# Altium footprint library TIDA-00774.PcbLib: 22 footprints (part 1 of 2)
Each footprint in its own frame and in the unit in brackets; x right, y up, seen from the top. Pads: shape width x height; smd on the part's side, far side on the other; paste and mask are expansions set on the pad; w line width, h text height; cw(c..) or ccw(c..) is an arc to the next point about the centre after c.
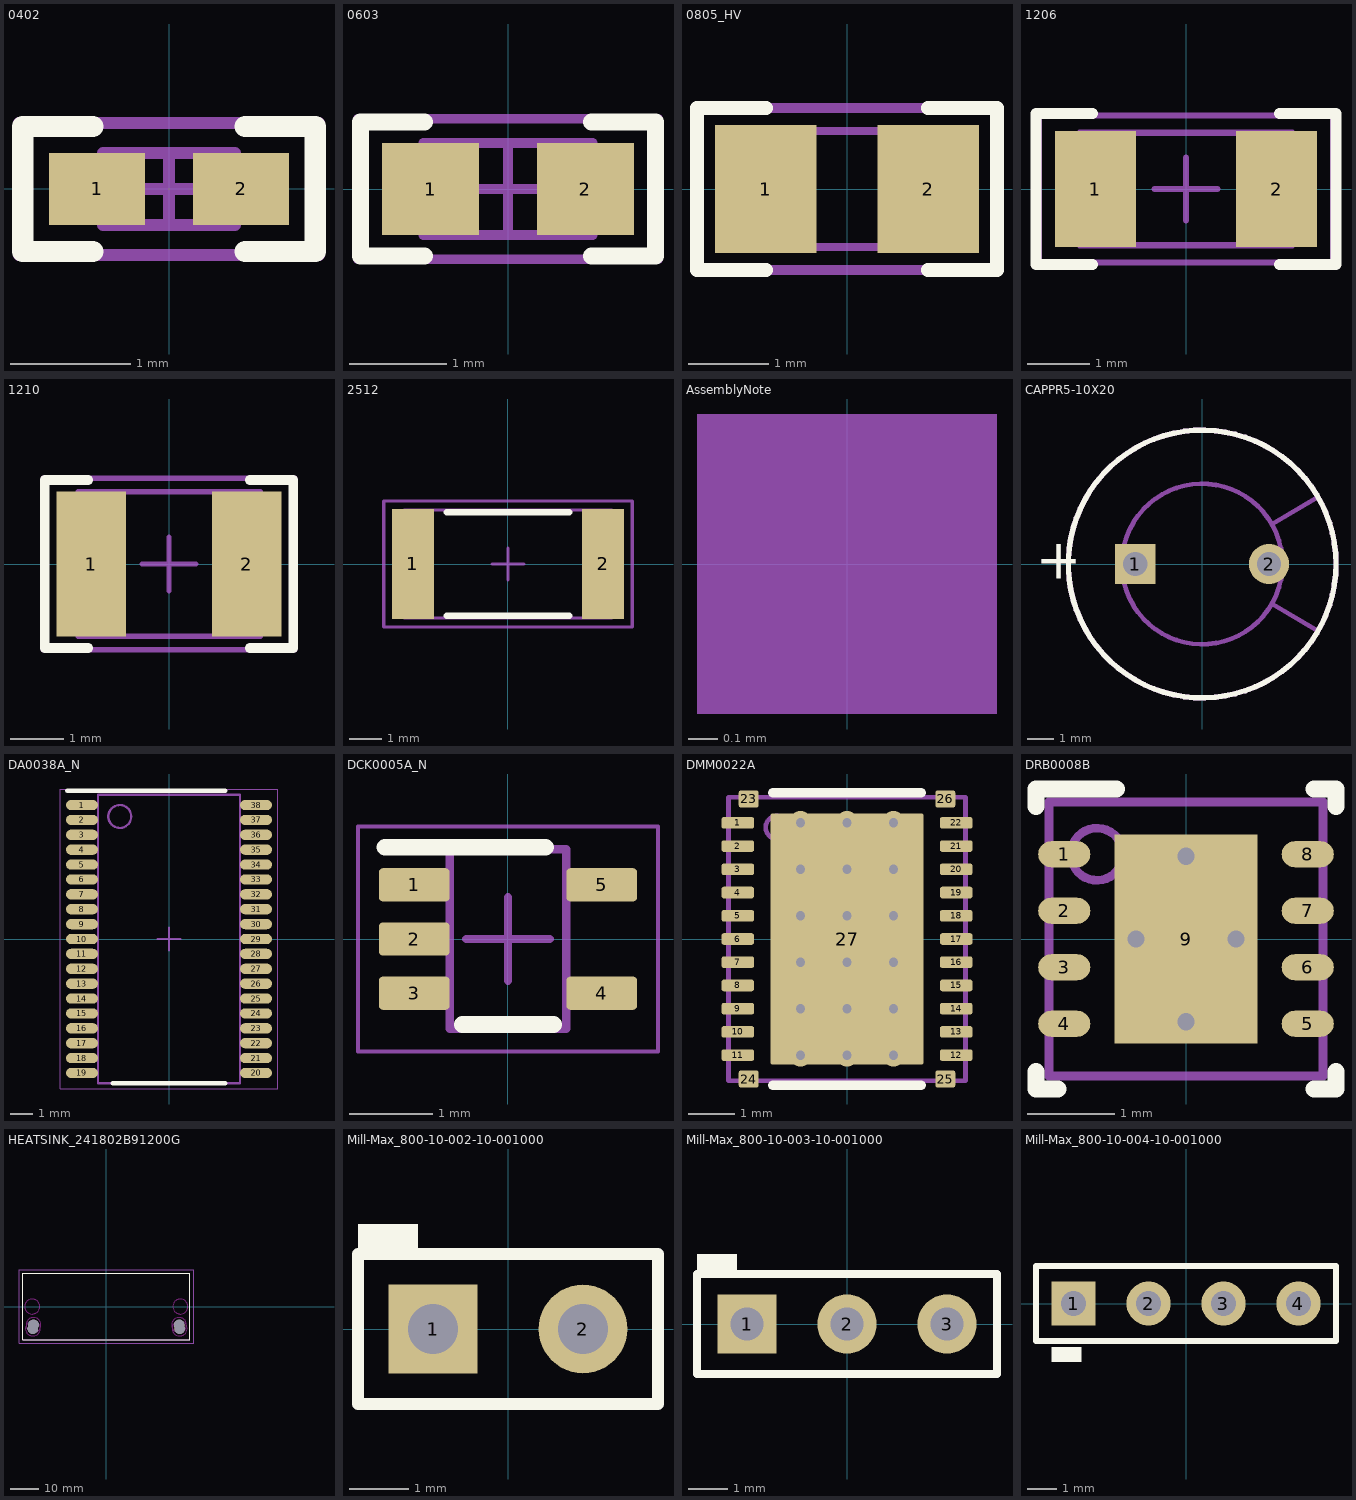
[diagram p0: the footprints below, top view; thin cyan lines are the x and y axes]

## 0402 [mm] "0402 from SM-752 data"
height 0.6
pads (2):
  rect 0.8x0.6 smd: 1(-0.6,0) 2(0.6,0)
Top Overlay:
  lines w0.178: -0.635,-0.521 -1.219,-0.521 -1.219,0.521 -0.635,0.521 ; 0.635,-0.521 1.219,-0.521 1.219,0.521 0.635,0.521
Mechanical 5:
  lines w0.1: -1.25,-0.55 1.25,-0.55 1.25,0.55 -1.25,0.55 -1.25,-0.55
  text ".Designator" at -1.117,-0.305 h0.61
Mechanical 13:
  lines w0.1: -0.35,-0.3 -0.35,0.3 ; 0.35,-0.3 0.35,0.3 ; -0.55,-0.3 -0.55,0.3 0.55,0.3 0.55,-0.3 -0.55,-0.3
Mechanical 15:
  lines w0.1: -0.3,0 0.3,0 ; 0,-0.3 0,0.3 ; -1.25,-0.55 -1.25,0.55 1.25,0.55 1.25,-0.55 -1.25,-0.55
3D body: height 0.6, standoff 0, extent -0.549,-0.299 -0.351,0.299
3D body: height 0.6, standoff 0, extent -0.349,-0.299 0.349,0.299
3D body: height 0.6, standoff 0, extent 0.351,-0.299 0.549,0.299

## 0603 [mm] "0603 from SM-752 data"
height 1
pads (2):
  rect 1x0.95 smd: 1(-0.8,0) 2(0.8,0)
Top Overlay:
  lines w0.178: -0.864,-0.691 -1.524,-0.691 -1.524,0.693 -0.864,0.693 ; 0.864,-0.691 1.524,-0.691 1.524,0.693 0.864,0.693
Mechanical 5:
  lines w0.1: -1.55,-0.725 1.55,-0.725 1.55,0.725 -1.55,0.725 -1.55,-0.725
  text ".Designator" at -1.397,-0.381 h0.76
Mechanical 13:
  lines w0.1: -0.55,-0.475 -0.55,0.475 ; 0.55,-0.475 0.55,0.475 ; -0.875,-0.475 -0.875,0.475 0.875,0.475 0.875,-0.475 -0.875,-0.475
Mechanical 15:
  lines w0.1: -0.475,0 0.475,0 ; 0,-0.475 0,0.475 ; -1.55,-0.725 -1.55,0.725 1.55,0.725 1.55,-0.725 -1.55,-0.725
3D body: height 1, standoff 0, extent 0.551,-0.474 0.874,0.474
3D body: height 1, standoff 0, extent -0.549,-0.474 0.549,0.474
3D body: height 1, standoff 0, extent -0.874,-0.474 -0.551,0.474

## 0805_HV [mil] "0805 with 30mil clearance between pads"
height 57.09
pads (2):
  rect 50x63 smd: 1(-40,0) 2(40,0)
Top Overlay:
  lines w7: -40,-40 -74,-40 -74,0 -74,40 -40,40 ; 40,-40 74,-40 74,0 74,40 40,40
Mechanical 5:
  lines w5: -74,-40 74,-40 74,40 -74,40 -74,-40
  text ".Designator" at -64,-17 h35
Mechanical 13:
  lines w3.94: -25.59,-28.54 -25.59,28.54 ; 25.59,-28.54 25.59,28.54 ; -43.31,-28.54 43.31,-28.54 43.31,28.54 -43.31,28.54 -43.31,-28.54
3D body: height 57.09, standoff 0, extent -43.29,-28.52 -25.61,28.52
3D body: height 57.09, standoff 0, extent -25.57,-28.52 25.57,28.52
3D body: height 57.09, standoff 0, extent 25.61,-28.52 43.29,28.52

## 1206 [mm] "1206 from SM-752 data"
height 1.35
pads (2):
  rect 1.3x1.85 smd: 1(-1.45,0) 2(1.45,0)
Top Overlay:
  lines w0.178: -1.5,-1.21 -2.4,-1.21 -2.4,1.21 -1.5,1.21 ; 1.5,-1.21 2.4,-1.21 2.4,1.21 1.5,1.21
Mechanical 5:
  lines w0.1: -1.7,-0.9 -1.7,0.9 1.7,0.9 1.7,-0.9 -1.7,-0.9
  text ".Designator" at -1.475,-0.4 h0.76
Mechanical 13:
  lines w0.1: -1.2,-0.9 -1.2,0.9 ; 1.2,-0.9 1.2,0.9 ; -1.7,-0.9 -1.7,0.9 1.7,0.9 1.7,-0.9 -1.7,-0.9
Mechanical 15:
  lines w0.1: -0.5,0 0.5,0 ; 0,-0.5 0,0.5 ; -2.35,-1.175 -2.35,1.175 2.35,1.175 2.35,-1.175 -2.35,-1.175
3D body: height 1.35, standoff 0, extent 1.201,-0.899 1.699,0.899
3D body: height 1.35, standoff 0, extent -1.199,-0.899 1.199,0.899
3D body: height 1.35, standoff 0, extent -1.699,-0.899 -1.201,0.899

## 1210 [mm] "1210 from SM-752 data"
height 1.35
pads (2):
  rect 1.3x2.7 smd: 1(-1.45,0) 2(1.45,0)
Top Overlay:
  lines w0.178: -1.511,-1.568 -2.316,-1.568 -2.316,1.568 -1.511,1.568 ; 1.511,-1.568 2.316,-1.568 2.316,1.568 1.511,1.568
Mechanical 5:
  lines w0.1: -1.7,-1.35 1.7,-1.35 1.7,1.35 -1.7,1.35 -1.7,-1.35
  text ".Designator" at -1.4,-0.375 h0.76
Mechanical 13:
  lines w0.1: -1.2,-1.35 -1.2,1.35 ; 1.2,-1.35 1.2,1.35 ; -1.7,-1.35 -1.7,1.35 1.7,1.35 1.7,-1.35 -1.7,-1.35
Mechanical 15:
  lines w0.1: -0.5,0 0.5,0 ; 0,-0.5 0,0.5 ; -2.35,-1.6 -2.35,1.6 2.35,1.6 2.35,-1.6 -2.35,-1.6
3D body: height 1.35, standoff 0, extent -1.699,-1.349 -1.201,1.349
3D body: height 1.35, standoff 0, extent -1.199,-1.349 1.199,1.349
3D body: height 1.35, standoff 0, extent 1.201,-1.349 1.699,1.349

## 2512 [mm] "Chip Resistor, Body 6.3x3.2mm, IPC Medium Density"
height 0.71
pads (2):
  rect 1.3x3.4 smd: 1(-2.95,0) 2(2.95,0)
Top Overlay:
  lines w0.2: -1.9,-1.6 1.9,-1.6 ; -1.9,1.6 1.9,1.6
Mechanical 5:
  lines w0.1: -3.225,-1.675 -3.225,1.675 3.225,1.675 3.225,-1.675 -3.225,-1.675
  text ".Designator" at -0.686,-0.305 h0.64
Mechanical 13:
  lines w0.1: -2.463,-1.675 -2.463,1.675 ; 2.463,-1.675 2.463,1.675 ; -3.225,-1.675 -3.225,1.675 3.225,1.675 3.225,-1.675 -3.225,-1.675
Mechanical 15:
  lines w0.1: -0.5,0 0.5,0 ; 0,-0.5 0,0.5 ; -3.85,-1.95 -3.85,1.95 3.85,1.95 3.85,-1.95 -3.85,-1.95
3D body: height 0.71, standoff 0, extent 2.464,-1.674 3.224,1.674
3D body: height 0.71, standoff 0, extent -2.462,-1.674 2.462,1.674
3D body: height 0.71, standoff 0, extent -3.224,-1.674 -2.464,1.674

## AssemblyNote [mm] "Assembly Note"
Mechanical 5:
  rectangle: -0.508,-0.508 0.508,0.508
  text ".Designator" at -4.191,-0.508 h0.64
  text ".Comment" at 1.143,-0.508 h0.64

## CAPPR5-10X20 [mm] "Capacitor, Electrolytic, Radial; Body 10 x 20 mm (Dia.xH typ); Pin Spacing 5 mm (typ)"
height 22
pads (2):
  rect 1.5x1.5 hole 0.9: 1(-2.5,0)
  round 1.5 hole 0.9: 2(2.5,0)
Top Overlay:
  circle w0.2: c0,0 r5
  text "+" at -6.208,-0.559 h1.5
Mechanical 5:
  circle w0.2: c0,0 r5
  text ".Designator" at 0.446,0.254 h0.64
  text "+" at -5.65,-0.025 h0.64
Mechanical 13:
  circle w0.178: c0,0 r3
  circle w0.178: c-2.5,0 r0.3
  circle w0.178: c2.5,0 r0.3
  lines w0.178: 2.623,-1.5 4.33,-2.5 cw(c0,0) 4.33,2.5 ; 2.623,1.5 4.33,2.5
3D body: height 22, standoff 0, extent 2.597,-2.5 5.001,2.5
3D body: height 22, standoff 0, extent -5,-5 4.329,5
3D body: height 22, standoff 0, extent -2.999,-2.999 2.999,2.999
3D body: height 1, standoff -2.54, extent -2.799,-0.299 -2.201,0.299
3D body: height 1, standoff -2.54, extent 2.201,-0.299 2.799,0.299

## DA0038A_N [mm] "TSOP, 38-Leads, Body 12.6x6.2mm (max), Pitch 0.65mm, IPC Medium Density"
height 1.2
pads (38):
  oval 1.4x0.45 smd: 1(-3.8,5.85) 2(-3.8,5.2) 3(-3.8,4.55) 4(-3.8,3.9) 5(-3.8,3.25) 6(-3.8,2.6) 7(-3.8,1.95) 8(-3.8,1.3) 9(-3.8,0.65) 10(-3.8,0) 11(-3.8,-0.65) 12(-3.8,-1.3) 13(-3.8,-1.95) 14(-3.8,-2.6) 15(-3.8,-3.25) 16(-3.8,-3.9) 17(-3.8,-4.55) 18(-3.8,-5.2) 19(-3.8,-5.85) 20(3.8,-5.85) 21(3.8,-5.2) 22(3.8,-4.55) 23(3.8,-3.9) 24(3.8,-3.25) 25(3.8,-2.6) 26(3.8,-1.95) 27(3.8,-1.3) 28(3.8,-0.65) 29(3.8,0) 30(3.8,0.65) 31(3.8,1.3) 32(3.8,1.95) 33(3.8,2.6) 34(3.8,3.25) 35(3.8,3.9) 36(3.8,4.55) 37(3.8,5.2) 38(3.8,5.85)
Top Overlay:
  lines w0.2: -4.45,6.475 2.45,6.475 ; -2.45,-6.3 2.45,-6.3
Mechanical 5:
  circle w0.1: c-2.15,5.35 r0.5
  lines w0.1: -3.1,-6.3 3.1,-6.3 3.1,6.3 -3.1,6.3 -3.1,-6.3
  text ".Designator" at -1.8,-0.7 h1
Mechanical 15:
  lines w0.05: -4.75,-6.55 -4.75,6.55 4.75,6.55 4.75,-6.55 -4.75,-6.55
  lines w0.1: -0.5,0 0.5,0 ; 0,-0.5 0,0.5
3D body "DA0038A_L.stp": height 1.2, standoff 0, extent -4.055,-6.25 4.056,6.25

## DCK0005A_N [mm] "SOT353, 5-Leads, Body 2x1.3mm, Pitch 0.65mm, Lead Span 2.1mm, IPC Medium Density"
height 1.1
pads (5):
  rrect25% 0.85x0.4 smd: 1(-1.125,0.65) 2(-1.125,0) 3(-1.125,-0.65) 4(1.125,-0.65) 5(1.125,0.65)
Top Overlay:
  lines w0.2: -1.475,1.1 0.45,1.1 ; -0.55,-1.025 0.55,-1.025
Mechanical 5:
  lines w0.1: -0.7,-1.075 -0.7,1.075 0.7,1.075 0.7,-1.075 -0.7,-1.075
  lines w0.127: -0.865,0.762 -0.853,0.762 ; -0.711,-0.763 -0.853,-0.763 -0.865,-0.763 -0.959,-0.763 -1.143,-0.763 -1.143,-0.538 -0.959,-0.538 -0.865,-0.538 -0.853,-0.538 -0.711,-0.538 ; -0.711,-0.113 -0.853,-0.113 -0.865,-0.113 -0.959,-0.113 -1.143,-0.113 -1.143,0.112 -0.959,0.112 -0.865,0.112 -0.853,0.112 -0.711,0.112 ; -0.711,0.537 -0.853,0.537 -0.865,0.537 -0.959,0.537 -1.143,0.537 -1.143,0.762 -0.959,0.762 -0.711,0.762 ; 0.711,-0.763 0.847,-0.763 0.859,-0.763 0.953,-0.763 1.137,-0.763 1.137,-0.538 0.953,-0.538 0.859,-0.538 0.847,-0.538 0.711,-0.538 ; 0.711,0.537 0.847,0.537 0.859,0.537 0.953,0.537 1.137,0.537 1.137,0.762 0.953,0.762 0.859,0.762 0.847,0.762 0.711,0.762
  text ".Designator" at -0.254,0.914 h0.51
Mechanical 15:
  lines w0.05: -1.8,-1.35 -1.8,1.35 1.8,1.35 1.8,-1.35 -1.8,-1.35
  lines w0.1: -0.5,0 0.5,0 ; 0,-0.5 0,0.5
3D body "DCK0005A.stp": height 0.95, standoff 0, extent -1.14,-1 1.14,1

## DMM0022A [mm] "SON, 27-Leads, Body 5x6mm, Pitch 0.5mm"
height 1.05
pads (35):
  rrect40% 0.7x0.25 smd mask+0.051: 1(-2.35,2.5) 2(-2.35,2) 21(2.35,2) 22(2.35,2.5)
  rrect40% 0.7x0.25 smd mask+0: 3(-2.35,1.5) 4(-2.35,1) 5(-2.35,0.5) 6(-2.35,0) 7(-2.35,-0.5) 8(-2.35,-1) 9(-2.35,-1.5) 10(-2.35,-2) 11(-2.35,-2.5) 12(2.35,-2.5) 13(2.35,-2) 14(2.35,-1.5) 15(2.35,-1) 16(2.35,-0.5) 17(2.35,0) 18(2.35,0.5) 19(2.35,1) 20(2.35,1.5)
  rrect27% 0.43x0.375 smd mask+0.051: 23(-2.115,3.013) 24(-2.115,-3.013) 25(2.115,-3.013) 26(2.115,3.013)
  rrect3% 3.3x5.4 smd paste-1.65: 27(0,0)
  rrect50% 1.41x1.12 on Top Paste: ""(-0.805,-1.98) ""(-0.805,-0.66) ""(-0.805,0.66) ""(-0.805,1.98) ""(0.805,-1.98) ""(0.805,-0.66) ""(0.805,0.66) ""(0.805,1.98)
via 1,0.501 diameter 0.5 hole 0.2
via 1,1.501 diameter 0.5 hole 0.2
via 1,-1.499 diameter 0.5 hole 0.2
via 1,-0.499 diameter 0.5 hole 0.2
via 1,-2.499 diameter 0.5 hole 0.2
via 0,0.501 diameter 0.5 hole 0.2
via 0,1.501 diameter 0.5 hole 0.2
via 0,-1.499 diameter 0.5 hole 0.2
via 0,-0.499 diameter 0.5 hole 0.2
via 0,-2.499 diameter 0.5 hole 0.2
via -1,-2.499 diameter 0.5 hole 0.2
via -1,-0.499 diameter 0.5 hole 0.2
via -1,-1.499 diameter 0.5 hole 0.2
via -1,1.501 diameter 0.5 hole 0.2
via -1,0.501 diameter 0.5 hole 0.2
via -1,2.501 diameter 0.5 hole 0.2
via 1,2.501 diameter 0.5 hole 0.2
via 0,2.501 diameter 0.5 hole 0.2
Top Overlay:
  lines w0.2: -1.6,-3.15 1.6,-3.15 ; -1.6,3.15 1.6,3.15
Mechanical 5:
  circle w0.1: c-1.5,2.4 r0.25
  lines w0.1: -2.55,-3.05 -2.55,3.05 2.55,3.05 2.55,-3.05 -2.55,-3.05
  text ".Designator" at -2,-0.7 h1.85
3D body: height 1.05, standoff 0, extent -2.55,-3.05 2.55,3.05
3D body: height 1.05, standoff 1.05, extent -1.749,2.151 -1.251,2.649

## DRB0008B [mm] "SON, 8-Leads, Body 3x3mm, Pitch 0.65mm, Thermal Pad 2.4x1.65mm, TI Recommended"
height 1
pads (9):
  oval 0.6x0.3 smd: 1(-1.4,0.975) 2(-1.4,0.325) 3(-1.4,-0.325) 4(-1.4,-0.975) 5(1.4,-0.975) 6(1.4,-0.325) 7(1.4,0.325) 8(1.4,0.975)
  rect 1.65x2.4 smd paste-1.2: 9(0,0)
via 0,-0.95 diameter 0.5 hole 0.2
via 0,0.95 diameter 0.5 hole 0.2
via 0.575,0 diameter 0.5 hole 0.2
via -0.575,0 diameter 0.5 hole 0.2
Top Overlay:
  lines w0.2: -1.725,-1.525 -1.725,-1.725 -1.475,-1.725 ; -1.725,1.525 -1.725,1.725 -0.8,1.725 ; 1.475,-1.725 1.725,-1.725 1.725,-1.525 ; 1.475,1.725 1.725,1.725 1.725,1.525
Top Paste:
  rectangle: -0.751,-1.143 0.752,-0.1
  rectangle: -0.751,0.1 0.752,1.143
Mechanical 5:
  circle w0.1: c-1.025,0.975 r0.3
  lines w0.1: -1.575,-1.575 -1.575,1.575 1.575,1.575 1.575,-1.575 -1.575,-1.575
  text ".Designator" at -1.397,-0.889 h0.76
3D body: height 1, standoff 0, extent -1.575,-1.575 1.575,1.575
3D body: height 1.01, standoff 0.5, extent -1.324,0.676 -0.726,1.274

## HEATSINK_241802B91200G [mm] "HEAT SINK, Mechanical part"
height 6.1
pads (4):
  round 3.654 hole 3.654 unplated mask+0.508: ""(-25.4,-7.6) ""(-25.2,-6.4) ""(25.2,-6.4) ""(25.4,-7.6)
Top Layer:
  lines w0.254: 25.168,-7.393 ccw(c25.4,-7.366) 25.524,-7.564
Top Overlay:
  lines w0.178: -28.95,-11.45 28.95,-11.45 28.95,11.45 -28.95,11.45 -28.95,-11.45
Keep-Out Layer:
  circle w0.025: c-25.65,0 r2.589
  circle w0.025: c25.65,0 r2.589
  circle w0.025: c-25.2,-6.4 r2.589
  circle w0.025: c-25.4,-7.6 r2.589
  circle w0.025: c25.2,-6.4 r2.589
  circle w0.025: c25.4,-7.6 r2.589
Mechanical 5:
  lines w0.127: -28.95,-11.45 28.95,-11.45 28.95,11.45 -28.95,11.45 -28.95,-11.45
  text ".Designator" at -0.381,0.909 h1.02
Mechanical 15:
  lines w0.05: -30.22,-12.72 30.22,-12.72 30.22,12.72 -30.22,12.72 -30.22,-12.72
Drill Drawing:
  lines w0.254: 26.5,-9.375 27.325,-10.2 ; 27.25,-6.65 29.65,-6.65 44.538,-6.65 ; 44.613,-10.2 29.725,-10.2 27.325,-10.2 ; 54.85,-16.425 54.342,-15.409 cw(c55.988,-14.399) 57.786,-13.694 ; 54.85,-14.625 55.875,-14.625 ; 54.883,-16.47 ccw(c56.593,-15.59) 58.386,-14.893 ; 55.35,-14.1 55.359,-15.04 ; 55.525,-16.1 56.55,-16.1 ; 56.025,-15.625 56.034,-16.565 ; 56.625,-14.55 67.675,-14.55 ; 56.75,-14.925 56.4,-14.575 56.75,-14.225 ; 57.275,-16.105 67.225,-16.105 ; 57.4,-16.5 57.05,-16.15 57.4,-15.8 ; 57.793,-13.692 58.358,-14.841 ; 66.625,-11.35 67.85,-11.35 ; 66.7,-15.1 67.35,-13.8 ; 66.703,-15.07 ccw(c68.405,-15.964) 70.026,-17 ; 67.125,-16.475 67.5,-16.1 67.138,-15.737 ; 67.325,-10.775 67.863,-11.312 ; 67.349,-13.865 cw(c69.041,-14.779) 70.718,-15.721 ; 67.363,-11.887 67.875,-11.375 ; 67.525,-14.975 67.975,-14.525 67.575,-14.125 ; 67.95,-16.125 68.975,-16.125 ; 68.45,-15.675 68.459,-16.615 ; 68.45,-15.275 68.45,-11.225 ; 68.725,-14.55 69.75,-14.55 ; 69.225,-14.1 69.234,-15.04 ; 69.25,-13.675 69.25,-11.2 ; 69.525,-16.175 73.275,-16.175 ; 69.725,-11.35 70.925,-11.35 ; 69.75,-11.375 70.288,-11.912 ; 69.763,-11.287 70.25,-10.8 ; 70.024,-16.972 70.687,-15.779 ; 70.275,-14.575 73.35,-14.575 ; 72.588,-17.187 73.075,-16.7 ; 72.6,-13.45 73.138,-13.987 ; 73.075,-17.675 73.075,-16.7 ; 73.15,-12.75 73.15,-13.987 73.138,-13.987 ; 73.538,-17.162 73.075,-16.7 ; 73.65,-13.475 73.138,-13.987 ; 27.325,-10.2 27.325,-10.2
  text "0.2 MM" at 70.475,-9.9 h1
  text "1.2 MM" at 74.35,-15.075 h1
  text "4 x SEE DETAIL A" at 56.825,-9.75 h1.52
  text "R1.7X 4" at 54.775,-5.9 h1.52
  text "50.4 MM (1.98\")" at 65.425,-16.75 h1
  text "DETAIL A" at 65.5,-18.35 h1.52
  text "50.8 MM (2.00\")" at 65.775,-15.05 h1
3D body: height 6.1, standoff 0, extent -28.95,-11.45 28.95,11.45

## Mill-Max_800-10-002-10-001000 [mm] "Mill-Max"
height 8.128
pads (2):
  rect 1.5x1.5 hole 0.85: 1(-1.27,0)
  round 1.5 hole 0.85: 2(1.27,0)
Top Overlay:
  rectangle: -2.54,1.27 -1.524,1.778
  lines w0.203: -2.54,-1.27 -2.54,1.27 2.54,1.27 2.54,-1.27 -2.54,-1.27
Mechanical 5:
  lines w0.102: -2.54,-1.27 2.54,-1.27 2.54,1.27 -2.54,1.27 -2.54,-1.27
  text ".Designator" at -2.032,-0.508 h0.76
3D body: height 0.81, standoff -3, extent -1.572,-0.304 -0.965,0.304
3D body: height 0.81, standoff -3, extent 0.968,-0.304 1.575,0.304
3D body: height 8.13, standoff 0, extent -1.648,-0.38 -0.889,0.38
3D body: height 8.13, standoff 0, extent 0.892,-0.38 1.651,0.38
3D body: height 3.17, standoff 0, extent -2.539,-1.269 2.539,1.269

## Mill-Max_800-10-003-10-001000 [mm] "Mill-Max"
height 8.128
pads (3):
  rect 1.5x1.5 hole 0.85: 1(-2.54,0)
  round 1.5 hole 0.85: 2(0,0) 3(2.54,0)
Top Overlay:
  rectangle: -3.81,1.27 -2.794,1.778
  lines w0.203: -3.81,-1.27 3.81,-1.27 3.81,1.27 -3.81,1.27 -3.81,-1.27
Mechanical 5:
  lines w0.102: -3.81,-1.27 -3.81,1.27 3.81,1.27 3.81,-1.27 -3.81,-1.27
  text ".Designator" at -2.032,-0.508 h0.76
3D body: height 8.13, standoff 0, extent 2.162,-0.38 2.921,0.38
3D body: height 8.13, standoff 0, extent -0.378,-0.38 0.381,0.38
3D body: height 8.13, standoff 0, extent -2.918,-0.38 -2.159,0.38
3D body: height 0.81, standoff -3, extent 2.238,-0.304 2.845,0.304
3D body: height 0.81, standoff -3, extent -0.302,-0.304 0.305,0.304
3D body: height 0.81, standoff -3, extent -2.842,-0.304 -2.235,0.304
3D body: height 3.17, standoff 0, extent -3.809,-1.269 3.809,1.269

## Mill-Max_800-10-004-10-001000 [mm] "Mill-Max"
height 8.128
pads (4):
  rect 1.5x1.5 hole 0.85: 1(-3.81,0)
  round 1.5 hole 0.85: 2(-1.27,0) 3(1.27,0) 4(3.81,0)
Top Overlay:
  rectangle: -4.547,-1.981 -3.531,-1.473
  lines w0.203: -5.08,-1.27 5.08,-1.27 5.08,1.27 -5.08,1.27 -5.08,-1.27
Mechanical 5:
  lines w0.102: -5.08,-1.27 -5.08,1.27 5.08,1.27 5.08,-1.27 -5.08,-1.27
  text ".Designator" at -0.921,-0.15 h0.76
3D body: height 3.17, standoff 0, extent -5.079,-1.269 5.079,1.269
3D body: height 8.13, standoff 0, extent 3.432,-0.38 4.191,0.38
3D body: height 8.13, standoff 0, extent 0.892,-0.38 1.651,0.38
3D body: height 8.13, standoff 0, extent -1.648,-0.38 -0.889,0.38
3D body: height 8.13, standoff 0, extent -4.188,-0.38 -3.429,0.38
3D body: height 0.81, standoff -3, extent 3.508,-0.304 4.115,0.304
3D body: height 0.81, standoff -3, extent 0.968,-0.304 1.575,0.304
3D body: height 0.81, standoff -3, extent -1.572,-0.304 -0.965,0.304
3D body: height 0.81, standoff -3, extent -4.112,-0.304 -3.505,0.304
